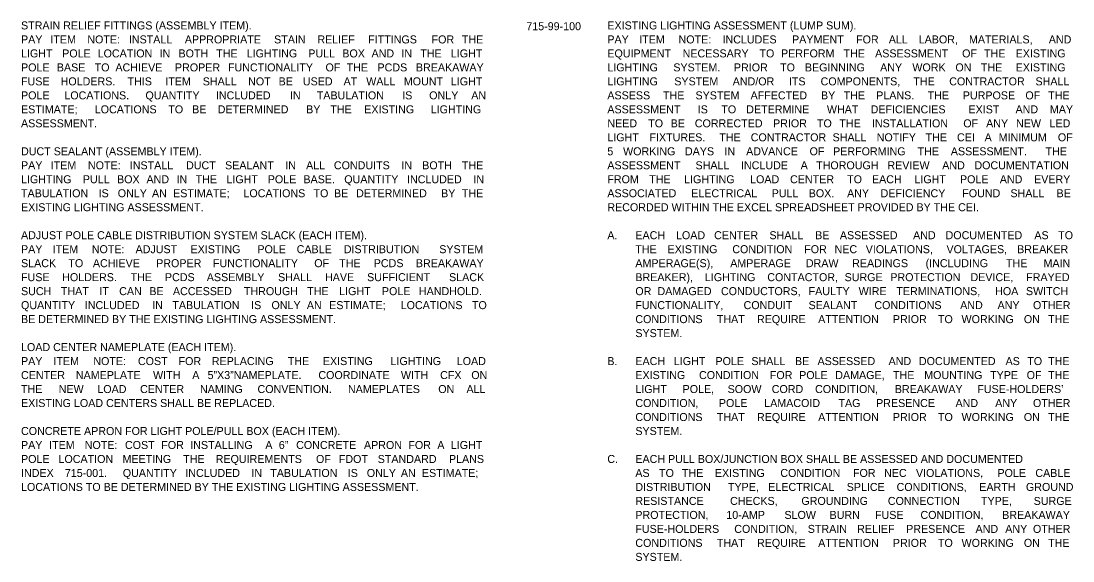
# Model space of a CAD drawing. Extents: x -55 to 2471539, y -90 to 3608906.
# Drawn here: x 599 to 1519, y 450 to 923 of the extents above; entities that cross this region are included whole.
import ezdxf

# ---------------------------------------------------------------- set-up
doc = ezdxf.new("R2010")
doc.units = 0
doc.layers.add('TextNotes', color=7, linetype='Continuous')

msp = doc.modelspace()

# ---------------------------------------------------------------- texts
at = {"layer": 'TextNotes'}
for s, p in [('STRAIN RELIEF FITTINGS (ASSEMBLY ITEM).', (598.8, 915.86)), ('715-99-100', (1040.87, 915.16)), ('EXISTING LIGHTING ASSESSMENT (LUMP SUM).', (1111.78, 915.86)), ('PAY ', (598.8, 903.61)), ('ITEM ', (624.52, 903.61)), ('NOTE: ', (656.81, 903.61)), ('INSTALL ', (693.17, 903.61)), ('APPROPRIATE ', (742.12, 903.61)), ('STAIN ', (820.22, 903.61)), ('RELIEF ', (858.07, 903.61)), ('FITTINGS ', (902.53, 903.61)), ('FOR ', (958, 903.61)), ('THE ', (984.48, 903.61)), ('PAY ', (1111.78, 903.61)), ('ITEM ', (1139.64, 903.61)), ('NOTE: ', (1174.06, 903.61)), ('INCLUDES ', (1212.55, 903.61)), ('PAYMENT ', (1273.39, 903.61)), ('FOR ', (1329.42, 903.61)), ('ALL ', (1358.03, 903.61)), ('LABOR, ', (1384.2, 903.61)), ('MATERIALS, ', (1428.19, 903.61)), ('AND ', (1498, 903.61)), ('LIGHT ', (598.8, 891.36)), ('POLE ', (634.82, 891.36)), ('LOCATION ', (665.83, 891.36)), ('IN ', (720.03, 891.36)), ('BOTH ', (736.59, 891.36)), ('THE ', (769.57, 891.36)), ('LIGHTING ', (796.24, 891.36)), ('PULL ', (850.14, 891.36)), ('BOX ', (879.9, 891.36)), ('AND ', (905.46, 891.36)), ('IN ', (931.6, 891.36)), ('THE ', (948.15, 891.36)), ('LIGHT ', (974.83, 891.36)), ('EQUIPMENT ', (1111.78, 891.36)), ('NECESSARY ', (1177.65, 891.36)), ('TO ', (1244.89, 891.36)), ('PERFORM ', (1263.72, 891.36)), ('THE ', (1318.38, 891.36)), ('ASSESSMENT ', (1346.05, 891.36)), ('OF ', (1422.18, 891.36)), ('THE ', (1441.35, 891.36)), ('EXISTING ', (1469.02, 891.36)), ('POLE ', (598.8, 879.11)), ('BASE ', (630.12, 879.11)), ('TO ', (663.23, 879.11)), ('ACHIEVE ', (681.39, 879.11)), ('PROPER ', (733.47, 879.11)), ('FUNCTIONALITY ', (779.86, 879.11)), ('OF ', (865.2, 879.11)), ('THE ', (883.7, 879.11)), ('PCDS ', (910.68, 879.11)), ('BREAKAWAY ', (944.28, 879.11)), ('LIGHTING ', (1111.78, 879.11)), ('SYSTEM. ', (1169.51, 879.11)), ('PRIOR ', (1222.51, 879.11)), ('TO ', (1262.94, 879.11)), ('BEGINNING ', (1284.61, 879.11)), ('ANY ', (1350.43, 879.11)), ('WORK ', (1378.63, 879.11)), ('ON ', (1416.3, 879.11)), ('THE ', (1438.53, 879.11)), ('EXISTING ', (1469.02, 879.11)), ('FUSE ', (598.8, 866.86)), ('HOLDERS. ', (633.45, 866.86)), ('THIS ', (691.98, 866.86)), ('ITEM ', (725.04, 866.86)), ('SHALL ', (757.82, 866.86)), ('NOT ', (797.49, 866.86)), ('BE ', (824.18, 866.86)), ('USED ', (845.4, 866.86)), ('AT ', (881.02, 866.86)), ('WALL ', (900.82, 866.86)), ('MOUNT ', (933.7, 866.86)), ('LIGHT ', (974.83, 866.86)), ('LIGHTING ', (1111.78, 866.86)), ('SYSTEM ', (1170.36, 866.86)), ('AND/OR ', (1221.46, 866.86)), ('ITS ', (1270.6, 866.86)), ('COMPONENTS, ', (1298.36, 866.86)), ('THE ', (1379.55, 866.86)), ('CONTRACTOR ', (1410.89, 866.86)), ('SHALL ', (1486.38, 866.86)), ('POLE ', (598.8, 854.61)), ('LOCATIONS. ', (636.72, 854.61)), ('QUANTITY ', (707.66, 854.61)), ('INCLUDED ', (769.3, 854.61)), ('IN ', (834.09, 854.61)), ('TABULATION ', (857.56, 854.61)), ('IS ', (932.31, 854.61)), ('ONLY ', (955.92, 854.61)), ('AN ', (992.71, 854.61)), ('ASSESS ', (1111.78, 854.61)), ('THE ', (1160.5, 854.61)), ('SYSTEM ', (1188.93, 854.61)), ('AFFECTED ', (1237.1, 854.61)), ('BY ', (1298.7, 854.61)), ('THE ', (1318.56, 854.61)), ('PLANS. ', (1346.99, 854.61)), (' THE ', (1389.44, 854.61)), ('PURPOSE ', (1422.78, 854.61)), ('OF ', (1477.53, 854.61)), ('THE ', (1497.47, 854.61)), ('ESTIMATE; ', (598.8, 842.36)), ('LOCATIONS ', (663.33, 842.36)), ('TO ', (727.65, 842.36)), ('BE ', (748.53, 842.36)), ('DETERMINED ', (770.88, 842.36)), ('BY ', (848.24, 842.36)), ('THE ', (869.38, 842.36)), ('EXISTING ', (899.09, 842.36)), ('LIGHTING ', (957.25, 842.36)), ('ASSESSMENT ', (1111.78, 842.36)), ('IS ', (1190.86, 842.36)), ('TO ', (1211.51, 842.36)), ('DETERMINE ', (1233.3, 842.36)), ('WHAT ', (1303.87, 842.36)), ('DEFICIENCIES ', (1342.13, 842.36)), ('EXIST ', (1427.71, 842.36)), ('AND ', (1468.89, 842.36)), ('MAY ', (1498.97, 842.36)), ('ASSESSMENT.', (598.8, 830.11)), ('NEED ', (1111.78, 830.11)), ('TO ', (1147.56, 830.11)), ('BE ', (1167.2, 830.11)), ('CORRECTED ', (1188.3, 830.11)), ('PRIOR ', (1256.76, 830.11)), ('TO ', (1295.16, 830.11)), ('THE ', (1314.8, 830.11)), ('INSTALLATION ', (1343.26, 830.11)), ('OF ', (1423.21, 830.11)), ('ANY ', (1443.19, 830.11)), ('NEW ', (1469.36, 830.11)), ('LED ', (1498.67, 830.11)), ('LIGHT ', (1111.78, 817.86)), ('FIXTURES. ', (1148.63, 817.86)), ('THE ', (1209.74, 817.86)), ('CONTRACTOR ', (1237.23, 817.86)), ('SHALL ', (1308.86, 817.86)), ('NOTIFY ', (1347.43, 817.86)), ('THE ', (1390.21, 817.86)), ('CEI ', (1417.7, 817.86)), ('A ', (1441.84, 817.86)), ('MINIMUM ', (1454.16, 817.86)), ('OF ', (1505.96, 817.86)), ('DUCT SEALANT (ASSEMBLY ITEM).', (598.8, 805.61)), ('5 ', (1111.78, 805.61)), ('WORKING ', (1125.56, 805.61)), ('DAYS ', (1179.68, 805.61)), ('IN ', (1214.27, 805.61)), ('ADVANCE ', (1233.23, 805.61)), ('OF ', (1288.7, 805.61)), ('PERFORMING ', (1309.28, 805.61)), ('THE ', (1383.21, 805.61)), ('ASSESSMENT. ', (1412.28, 805.61)), (' THE ', (1492.56, 805.61)), ('PAY ', (598.8, 793.36)), ('ITEM ', (624.79, 793.36)), ('NOTE: ', (657.34, 793.36)), ('INSTALL ', (693.97, 793.36)), ('DUCT ', (743.18, 793.36)), ('SEALANT ', (777.3, 793.36)), ('IN ', (829.98, 793.36)), ('ALL ', (848.23, 793.36)), ('CONDUITS ', (872.53, 793.36)), ('IN ', (931.56, 793.36)), ('BOTH ', (949.81, 793.36)), ('THE ', (984.48, 793.36)), ('ASSESSMENT ', (1111.78, 793.36)), ('SHALL ', (1188.93, 793.36)), ('INCLUDE ', (1228.7, 793.36)), ('A ', (1280.92, 793.36)), ('THOROUGH ', (1294.44, 793.36)), ('REVIEW ', (1356.8, 793.36)), ('AND ', (1404.77, 793.36)), ('DOCUMENTATION ', (1432.92, 793.36)), ('LIGHTING ', (598.8, 781.11)), ('PULL ', (652.88, 781.11)), ('BOX ', (682.82, 781.11)), ('AND ', (708.57, 781.11)), ('IN ', (734.88, 781.11)), ('THE ', (751.62, 781.11)), ('LIGHT ', (778.48, 781.11)), ('POLE ', (814.68, 781.11)), ('BASE. ', (845.87, 781.11)), ('QUANTITY ', (881.61, 781.11)), ('INCLUDED ', (936.53, 781.11)), ('IN ', (994.59, 781.11)), ('FROM ', (1111.78, 781.11)), ('THE ', (1148.42, 781.11)), ('LIGHTING ', (1178.94, 781.11)), ('LOAD ', (1236.69, 781.11)), ('CENTER ', (1271.65, 781.11)), ('TO ', (1321.61, 781.11)), ('EACH ', (1343.3, 781.11)), ('LIGHT ', (1380.42, 781.11)), ('POLE ', (1420.29, 781.11)), ('AND ', (1455.15, 781.11)), ('EVERY ', (1485.13, 781.11)), ('TABULATION ', (598.8, 768.86)), ('IS ', (666.69, 768.86)), ('ONLY ', (683.44, 768.86)), ('AN ', (713.37, 768.86)), ('ESTIMATE; ', (731.86, 768.86)), ('LOCATIONS ', (793.4, 768.86)), ('TO ', (854.73, 768.86)), ('BE ', (872.61, 768.86)), ('DETERMINED ', (891.97, 768.86)), ('BY ', (966.33, 768.86)), ('THE ', (984.48, 768.86)), ('ASSOCIATED ', (1111.78, 768.86)), ('ELECTRICAL ', (1185.16, 768.86)), ('PULL ', (1255.57, 768.86)), ('BOX. ', (1287.97, 768.86)), (' ANY ', (1318.92, 768.86)), ('DEFICIENCY ', (1350.84, 768.86)), ('FOUND ', (1422.3, 768.86)), ('SHALL ', (1464.45, 768.86)), ('BE ', (1504.83, 768.86)), ('EXISTING LIGHTING ASSESSMENT.', (598.8, 756.61)), ('RECORDED WITHIN THE EXCEL SPREADSHEET PROVIDED BY THE CEI. ', (1111.78, 756.61)), ('ADJUST POLE CABLE DISTRIBUTION SYSTEM SLACK (EACH ITEM).', (598.8, 732.11)), ('A.', (1111.78, 732.11)), ('EACH ', (1136.28, 732.11)), ('LOAD ', (1171.83, 732.11)), ('CENTER ', (1205.22, 732.11)), ('SHALL ', (1253.61, 732.11)), ('BE ', (1293.64, 732.11)), ('ASSESSED ', (1315.22, 732.11)), ('AND ', (1379.28, 732.11)), ('DOCUMENTED ', (1407.69, 732.11)), ('AS ', (1485.38, 732.11)), ('TO ', (1506.24, 732.11)), ('PAY ', (598.8, 719.86)), ('ITEM ', (626.48, 719.86)), ('NOTE: ', (660.71, 719.86)), ('ADJUST ', (699.02, 719.86)), ('EXISTING ', (747.11, 719.86)), ('POLE ', (805.6, 719.86)), ('CABLE ', (839.98, 719.86)), ('DISTRIBUTION ', (881.19, 719.86)), ('SYSTEM ', (964.73, 719.86)), ('THE ', (1136.28, 719.86)), ('EXISTING ', (1164.47, 719.86)), ('CONDITION ', (1221.1, 719.86)), ('FOR ', (1284.01, 719.86)), ('NEC ', (1310.59, 719.86)), ('VIOLATIONS, ', (1337.83, 719.86)), ('VOLTAGES, ', (1408.49, 719.86)), ('BREAKER ', (1470.32, 719.86)), ('SLACK ', (598.8, 707.61)), ('TO ', (640.24, 707.61)), ('ACHIEVE ', (661.68, 707.61)), ('PROPER ', (717.05, 707.61)), ('FUNCTIONALITY ', (766.72, 707.61)), ('OF ', (855.35, 707.61)), ('THE ', (877.13, 707.61)), ('PCDS ', (907.4, 707.61)), ('BREAKAWAY ', (944.28, 707.61)), ('AMPERAGE(S), ', (1136.28, 707.61)), ('AMPERAGE ', (1219.29, 707.61)), ('DRAW ', (1285.46, 707.61)), ('READINGS ', (1325.98, 707.61)), ('(INCLUDING ', (1390.23, 707.61)), ('THE ', (1460.62, 707.61)), ('MAIN ', (1493.39, 707.61)), ('FUSE ', (598.8, 695.36)), ('HOLDERS. ', (634.83, 695.36)), ('THE ', (694.75, 695.36)), ('PCDS ', (724.73, 695.36)), ('ASSEMBLY ', (761.32, 695.36)), ('SHALL ', (823.71, 695.36)), ('HAVE ', (864.76, 695.36)), ('SUFFICIENT ', (901.61, 695.36)), ('SLACK ', (973.3, 695.36)), ('BREAKER), ', (1136.28, 695.36)), ('LIGHTING ', (1197.13, 695.36)), ('CONTACTOR, ', (1251.71, 695.36)), ('SURGE ', (1319.38, 695.36)), ('PROTECTION ', (1359.36, 695.36)), ('DEVICE, ', (1429.52, 695.36)), ('FRAYED ', (1478.23, 695.36)), ('SUCH ', (598.8, 683.11)), ('THAT ', (633.66, 683.11)), ('IT ', (667.34, 683.11)), ('CAN ', (684.69, 683.11)), ('BE ', (711.06, 683.11)), ('ACCESSED ', (731.72, 683.11)), ('THROUGH ', (793.82, 683.11)), ('THE ', (849.14, 683.11)), ('LIGHT ', (877.17, 683.11)), ('POLE ', (914.54, 683.11)), ('HANDHOLD. ', (946.91, 683.11)), ('OR ', (1136.28, 683.11)), ('DAMAGED ', (1155.62, 683.11)), ('CONDUCTORS, ', (1211.18, 683.11)), ('FAULTY ', (1287.86, 683.11)), ('WIRE ', (1331.65, 683.11)), ('TERMINATIONS, ', (1364.63, 683.11)), ('HOA ', (1451.07, 683.11)), ('SWITCH ', (1478.02, 683.11)), ('QUANTITY ', (598.8, 670.86)), ('INCLUDED ', (654.61, 670.86)), ('IN ', (713.57, 670.86)), ('TABULATION ', (731.21, 670.86)), ('IS ', (800.13, 670.86)), ('ONLY ', (817.91, 670.86)), ('AN ', (848.86, 670.86)), ('ESTIMATE; ', (868.39, 670.86)), ('LOCATIONS ', (930.96, 670.86)), ('TO ', (993.31, 670.86)), ('FUNCTIONALITY, ', (1136.28, 670.86)), ('CONDUIT ', (1230.97, 670.86)), ('SEALANT ', (1287.82, 670.86)), ('CONDITIONS ', (1345.41, 670.86)), ('AND ', (1420.47, 670.86)), ('ANY ', (1453.19, 670.86)), ('OTHER ', (1484.16, 670.86)), ('BE DETERMINED BY THE EXISTING LIGHTING ASSESSMENT.', (598.8, 658.61)), ('CONDITIONS ', (1136.28, 658.61)), ('THAT ', (1207.56, 658.61)), ('REQUIRE ', (1242.7, 658.61)), ('ATTENTION ', (1296.24, 658.61)), ('PRIOR ', (1361.6, 658.61)), ('TO ', (1401.02, 658.61)), ('WORKING ', (1421.67, 658.61)), ('ON ', (1476.2, 658.61)), ('THE ', (1497.41, 658.61)), ('SYSTEM.', (1136.28, 646.36)), ('LOAD CENTER NAMEPLATE (EACH ITEM).', (598.8, 634.11)), ('PAY ', (598.8, 621.86)), ('ITEM ', (627.16, 621.86)), ('NOTE: ', (662.08, 621.86)), ('COST ', (701.08, 621.86)), ('FOR ', (736.62, 621.86)), ('REPLACING ', (765.74, 621.86)), ('THE ', (832.17, 621.86)), ('EXISTING ', (862.9, 621.86)), ('LIGHTING ', (922.07, 621.86)), ('LOAD ', (980.04, 621.86)), ('B.', (1111.78, 621.86)), ('EACH ', (1136.28, 621.86)), ('LIGHT ', (1169.96, 621.86)), ('POLE ', (1206.38, 621.86)), ('SHALL ', (1237.8, 621.86)), ('BE ', (1275.95, 621.86)), ('ASSESSED ', (1295.66, 621.86)), ('AND ', (1357.84, 621.86)), ('DOCUMENTED ', (1384.37, 621.86)), ('AS ', (1460.19, 621.86)), ('TO ', (1479.18, 621.86)), ('THE ', (1497.41, 621.86)), ('CENTER ', (598.8, 609.61)), ('5”X3”NAMEPLATE. ', (762, 609.61)), ('COORDINATE ', (858.95, 609.61)), ('CFX ', (965.48, 609.61)), ('ON ', (992.75, 609.61)), ('EXISTING ', (1136.28, 609.61)), ('CONDITION ', (1191.98, 609.61)), ('FOR ', (1253.96, 609.61)), ('POLE ', (1279.6, 609.61)), ('DAMAGE, ', (1311.2, 609.61)), ('MOUNTING ', (1388.99, 609.61)), ('OF ', (1478.65, 609.61)), ('NAMEPLATE ', (646.79, 609.61)), ('WITH ', (714.31, 609.61)), ('A ', (748.62, 609.61)), ('WITH ', (931.18, 609.61)), ('THE ', (1361.73, 609.61)), ('TYPE ', (1446.66, 609.61)), ('THE ', (1497.41, 609.61)), ('THE ', (598.8, 597.36)), ('NEW ', (631.76, 597.36)), ('LOAD ', (665.57, 597.36)), ('CENTER ', (702.97, 597.36)), ('NAMING ', (755.38, 597.36)), ('CONVENTION. ', (805.71, 597.36)), ('NAMEPLATES ', (884.84, 597.36)), ('ON ', (963.85, 597.36)), ('ALL ', (988.54, 597.36)), ('LIGHT ', (1136.28, 597.36)), ('POLE, ', (1177.63, 597.36)), ('SOOW ', (1217.02, 597.36)), ('CORD ', (1255.61, 597.36)), ('CONDITION, ', (1293.51, 597.36)), ('BREAKAWAY ', (1363.29, 597.36)), ('FUSE-HOLDERS’ ', (1435.47, 597.36)), ('EXISTING LOAD CENTERS SHALL BE REPLACED.', (598.8, 585.11)), ('CONDITION, ', (1136.28, 585.11)), ('POLE ', (1209.37, 585.11)), ('LAMACOID ', (1249.02, 585.11)), ('TAG ', (1314, 585.11)), ('PRESENCE ', (1346.93, 585.11)), ('AND ', (1416.38, 585.11)), ('ANY ', (1451.15, 585.11)), ('OTHER ', (1484.16, 585.11)), ('CONDITIONS ', (1136.28, 572.86)), ('THAT ', (1207.56, 572.86)), ('REQUIRE ', (1242.7, 572.86)), ('ATTENTION ', (1296.24, 572.86)), ('PRIOR ', (1361.6, 572.86)), ('TO ', (1401.02, 572.86)), ('WORKING ', (1421.67, 572.86)), ('ON ', (1476.2, 572.86)), ('THE ', (1497.41, 572.86)), ('CONCRETE APRON FOR LIGHT POLE/PULL BOX (EACH ITEM).', (598.8, 560.61)), ('SYSTEM.', (1136.28, 560.61)), ('PAY ', (598.8, 548.36)), ('ITEM ', (623.38, 548.36)), ('NOTE: ', (654.53, 548.36)), ('COST ', (689.75, 548.36)), ('FOR ', (721.51, 548.36)), ('INSTALLING ', (746.85, 548.36)), ('A ', (812.54, 548.36)), ('6” ', (824.33, 548.36)), ('CONCRETE ', (839.52, 548.36)), ('APRON ', (898.85, 548.36)), ('FOR ', (937.69, 548.36)), ('A ', (963.03, 548.36)), ('LIGHT ', (974.83, 548.36)), ('POLE ', (598.8, 536.11)), ('LOCATION ', (631.59, 536.11)), ('MEETING ', (687.56, 536.11)), ('THE ', (740.68, 536.11)), ('REQUIREMENTS ', (769.13, 536.11)), ('OF ', (856.89, 536.11)), ('FDOT ', (876.85, 536.11)), ('STANDARD ', (910.87, 536.11)), ('PLANS ', (973.21, 536.11)), ('C.', (1111.78, 536.11)), ('EACH PULL BOX/JUNCTION BOX SHALL BE ASSESSED AND DOCUMENTED ', (1136.28, 536.11)), ('INDEX ', (598.8, 523.86)), ('715-001. ', (637.15, 523.86)), ('QUANTITY ', (687.83, 523.86)), ('INCLUDED ', (742.52, 523.86)), ('IN ', (800.35, 523.86)), ('TABULATION ', (816.86, 523.86)), ('IS ', (884.66, 523.86)), ('ONLY ', (901.31, 523.86)), ('AN ', (931.14, 523.86)), ('ESTIMATE; ', (949.54, 523.86)), ('AS ', (1136.28, 523.86)), ('TO ', (1157.03, 523.86)), ('THE ', (1177.03, 523.86)), ('EXISTING ', (1205.86, 523.86)), ('CONDITION ', (1263.13, 523.86)), ('FOR ', (1326.68, 523.86)), ('NEC ', (1353.9, 523.86)), ('VIOLATIONS, ', (1381.79, 523.86)), ('POLE ', (1453.09, 523.86)), ('CABLE ', (1486.26, 523.86)), ('LOCATIONS TO BE DETERMINED BY THE EXISTING LIGHTING ASSESSMENT.', (598.8, 511.61)), ('DISTRIBUTION ', (1136.28, 511.61)), ('TYPE, ', (1217.29, 511.61)), ('ELECTRICAL ', (1252.58, 511.61)), ('SPLICE ', (1321.19, 511.61)), ('CONDITIONS, ', (1364.84, 511.61)), ('EARTH ', (1437.2, 511.61)), ('GROUND ', (1478, 511.61)), ('RESISTANCE ', (1136.28, 499.36)), ('CHECKS, ', (1219.17, 499.36)), ('GROUNDING ', (1281.55, 499.36)), ('CONNECTION ', (1357.18, 499.36)), ('TYPE, ', (1438.66, 499.36)), ('SURGE ', (1484.79, 499.36)), ('PROTECTION, ', (1136.28, 487.11)), ('10-AMP ', (1215.87, 487.11)), ('SLOW ', (1266.74, 487.11)), ('BURN ', (1306.23, 487.11)), ('FUSE ', (1345.96, 487.11)), ('CONDITION, ', (1385.73, 487.11)), ('BREAKAWAY ', (1457.22, 487.11)), ('FUSE-HOLDERS ', (1136.28, 474.86)), ('CONDITION, ', (1222.82, 474.86)), ('STRAIN ', (1287.14, 474.86)), ('RELIEF ', (1330.32, 474.86)), ('PRESENCE ', (1373.22, 474.86)), ('AND ', (1433.91, 474.86)), ('ANY ', (1459.92, 474.86)), ('OTHER ', (1484.16, 474.86)), ('CONDITIONS ', (1136.28, 462.61)), ('THAT ', (1207.56, 462.61)), ('REQUIRE ', (1242.7, 462.61)), ('ATTENTION ', (1296.24, 462.61)), ('PRIOR ', (1361.6, 462.61)), ('TO ', (1401.02, 462.61)), ('WORKING ', (1421.67, 462.61)), ('ON ', (1476.2, 462.61)), ('THE ', (1497.41, 462.61)), ('SYSTEM.', (1136.28, 450.36))]:
    msp.add_text(s, height=7, dxfattribs=at).set_placement(p)

doc.saveas('drawing.dxf')
